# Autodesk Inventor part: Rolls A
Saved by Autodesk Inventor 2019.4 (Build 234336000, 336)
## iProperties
Created: 2020-05
Part Number: Rolls A
Material: Generic
Document SubType Name: Modeling
Designer: Administrator
Density: 1 g/cm^3
Appearance: Default
Title: Rolls A
Author: Administrator
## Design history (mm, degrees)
feature "Body1"
feature "Body2"
feature "Body3"
feature "Body4"
feature "Body21"
feature "Body22"
feature "Body23"
feature "Body24"
feature "Body25"
feature "Body26"
feature "Body29"
feature "Body30"
feature "Body31"
feature "Body33"
feature "Body34"
feature "Body35"
feature "Body36"
feature "Body37"
body "Solid1"
body "Solid2"
body "Solid3"
body "Solid4"
body "Solid5"
body "Solid6"
body "Solid7"
body "Solid8"
body "Solid9"
body "Solid10"
body "Solid11"
body "Solid12"
body "Solid13"
body "Solid14"
body "Solid15"
body "Solid16"
body "Solid17"
body "Solid18"
